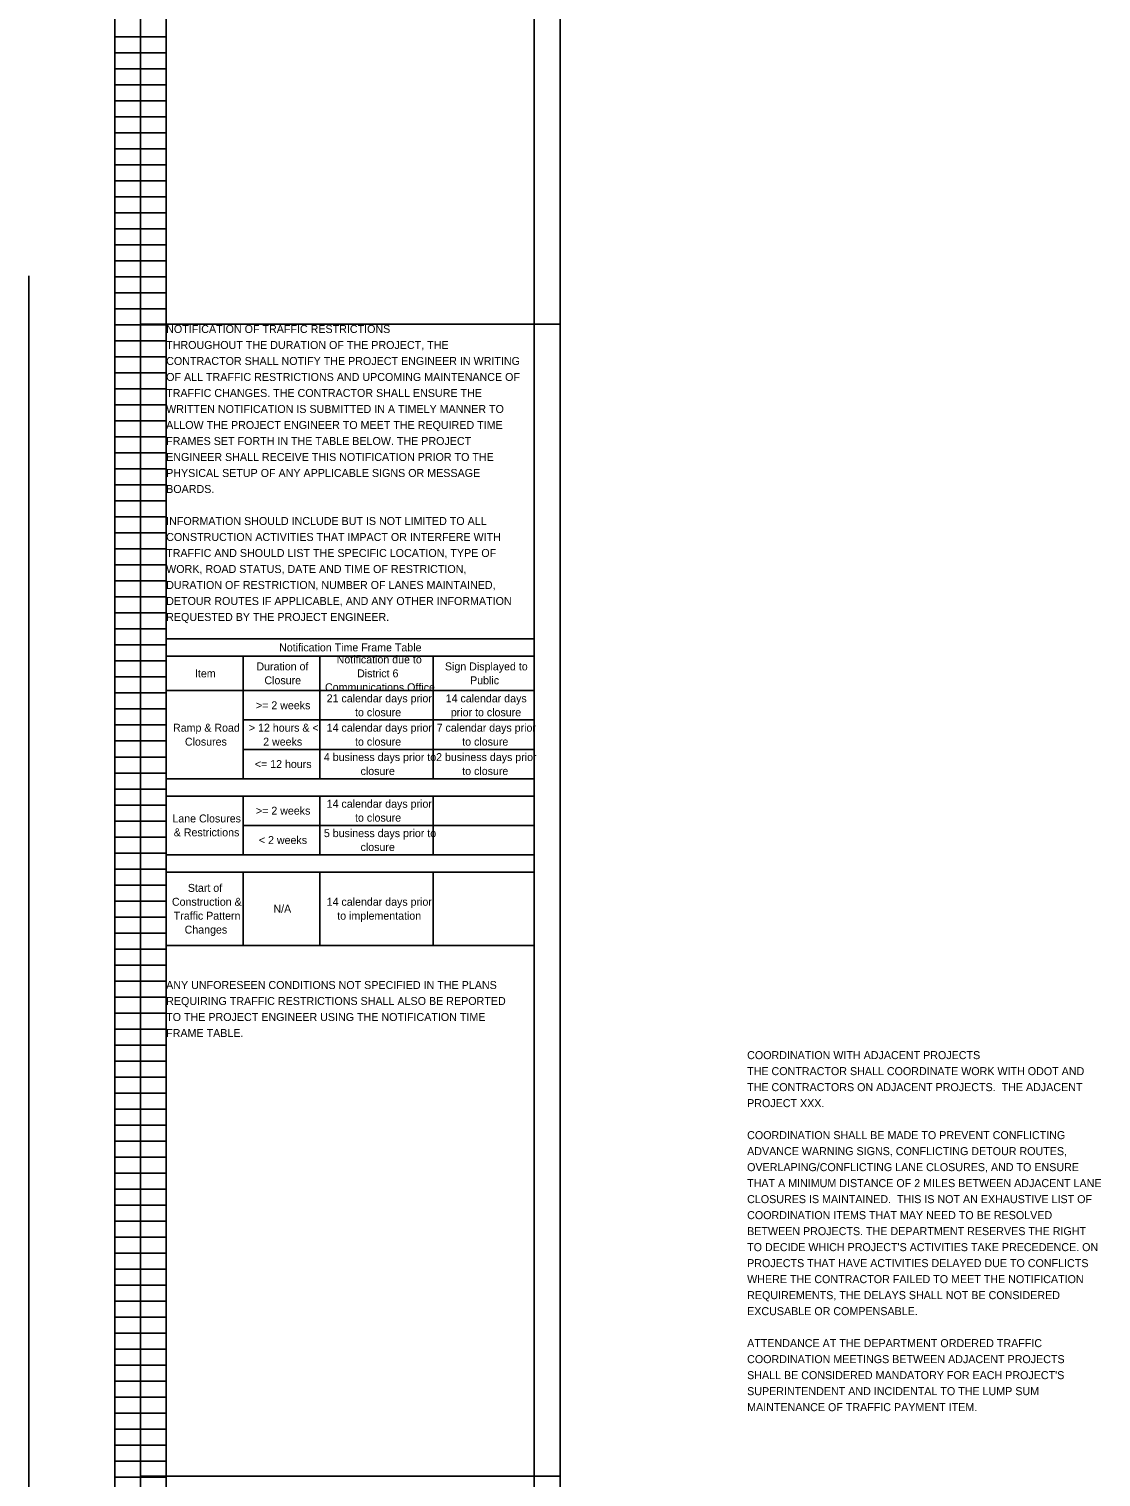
# Model space of a CAD drawing. Extents: x 0 to 19, y -301 to 22.
# Drawn here: x 0 to 18.75, y -79.66 to -54.32 of the extents above; entities that cross this region are included whole.
import ezdxf

# ---------------------------------------------------------------- set-up
doc = ezdxf.new("R2010")
doc.units = 0
doc.layers.add('SC_Scratch1', color=7, linetype='Continuous')
doc.layers.add('SH_Text', color=7, linetype='Continuous')

msp = doc.modelspace()

# ---------------------------------------------------------------- linework, layer by layer
at = {"layer": 'SC_Scratch1'}
for p, q in [((1.5, -59.5), (1.5, -39.34)), ((2.4, -59.5), (2.4, -39.34)), ((8.84, -59.5), (8.84, -39.34)), ((1.5, -54.46), (2.4, -54.46)), ((1.5, -54.74), (2.4, -54.74)), ((1.5, -55.02), (2.4, -55.02)), ((1.5, -55.3), (2.4, -55.3)), ((1.5, -55.58), (2.4, -55.58)), ((1.5, -55.86), (2.4, -55.86)), ((1.5, -56.14), (2.4, -56.14)), ((1.5, -56.42), (2.4, -56.42)), ((1.5, -56.7), (2.4, -56.7)), ((1.5, -56.98), (2.4, -56.98)), ((1.5, -57.26), (2.4, -57.26)), ((1.5, -57.54), (2.4, -57.54)), ((1.5, -57.82), (2.4, -57.82)), ((1.5, -58.1), (2.4, -58.1)), ((1.5, -58.38), (2.4, -58.38)), ((0, -58.64), (0, -80.64)), ((1.5, -58.66), (2.4, -58.66)), ((1.5, -58.94), (2.4, -58.94)), ((1.5, -59.22), (2.4, -59.22)), ((1.5, -59.5), (2.4, -59.5)), ((1.5, -59.5), (2.4, -59.5)), ((1.5, -79.66), (1.5, -59.5)), ((2.4, -79.66), (2.4, -59.5)), ((8.84, -79.66), (8.84, -59.5)), ((1.5, -59.78), (2.4, -59.78)), ((1.5, -60.06), (2.4, -60.06)), ((1.5, -60.34), (2.4, -60.34)), ((1.5, -60.62), (2.4, -60.62)), ((1.5, -60.9), (2.4, -60.9)), ((1.5, -61.18), (2.4, -61.18)), ((1.5, -61.46), (2.4, -61.46)), ((1.5, -61.74), (2.4, -61.74)), ((1.5, -62.02), (2.4, -62.02)), ((1.5, -62.3), (2.4, -62.3)), ((1.5, -62.58), (2.4, -62.58)), ((1.5, -62.86), (2.4, -62.86)), ((1.5, -63.14), (2.4, -63.14)), ((1.5, -63.42), (2.4, -63.42)), ((1.5, -63.7), (2.4, -63.7)), ((1.5, -63.98), (2.4, -63.98)), ((1.5, -64.26), (2.4, -64.26)), ((1.5, -64.54), (2.4, -64.54)), ((1.5, -64.82), (2.4, -64.82)), ((1.5, -65.1), (2.4, -65.1)), ((1.5, -65.38), (2.4, -65.38)), ((1.5, -65.66), (2.4, -65.66)), ((1.5, -65.94), (2.4, -65.94)), ((1.5, -66.22), (2.4, -66.22)), ((1.5, -66.5), (2.4, -66.5)), ((1.5, -66.78), (2.4, -66.78)), ((1.5, -67.06), (2.4, -67.06)), ((1.5, -67.34), (2.4, -67.34)), ((1.5, -67.62), (2.4, -67.62)), ((1.5, -67.9), (2.4, -67.9)), ((1.5, -68.18), (2.4, -68.18)), ((1.5, -68.46), (2.4, -68.46)), ((1.5, -68.74), (2.4, -68.74)), ((1.5, -69.02), (2.4, -69.02)), ((1.5, -69.3), (2.4, -69.3)), ((1.5, -69.58), (2.4, -69.58)), ((1.5, -69.86), (2.4, -69.86)), ((1.5, -70.14), (2.4, -70.14)), ((1.5, -70.42), (2.4, -70.42)), ((1.5, -70.7), (2.4, -70.7)), ((1.5, -70.98), (2.4, -70.98)), ((1.5, -71.26), (2.4, -71.26)), ((1.5, -71.54), (2.4, -71.54)), ((1.5, -71.82), (2.4, -71.82)), ((1.5, -72.1), (2.4, -72.1)), ((1.5, -72.38), (2.4, -72.38)), ((1.5, -72.66), (2.4, -72.66)), ((1.5, -72.94), (2.4, -72.94)), ((1.5, -73.22), (2.4, -73.22)), ((1.5, -73.5), (2.4, -73.5)), ((1.5, -73.78), (2.4, -73.78)), ((1.5, -74.06), (2.4, -74.06)), ((1.5, -74.34), (2.4, -74.34)), ((1.5, -74.62), (2.4, -74.62)), ((1.5, -74.9), (2.4, -74.9)), ((1.5, -75.18), (2.4, -75.18)), ((1.5, -75.46), (2.4, -75.46)), ((1.5, -75.74), (2.4, -75.74)), ((1.5, -76.02), (2.4, -76.02)), ((1.5, -76.3), (2.4, -76.3)), ((1.5, -76.58), (2.4, -76.58)), ((1.5, -76.86), (2.4, -76.86)), ((1.5, -77.14), (2.4, -77.14)), ((1.5, -77.42), (2.4, -77.42)), ((1.5, -77.7), (2.4, -77.7)), ((1.5, -77.98), (2.4, -77.98)), ((1.5, -78.26), (2.4, -78.26)), ((1.5, -78.54), (2.4, -78.54)), ((1.5, -78.82), (2.4, -78.82)), ((1.5, -79.1), (2.4, -79.1)), ((1.5, -79.38), (2.4, -79.38)), ((1.5, -79.66), (2.4, -79.66)), ((1.5, -79.66), (2.4, -79.66)), ((1.5, -99.82), (1.5, -79.66)), ((2.4, -99.82), (2.4, -79.66)), ((8.84, -99.82), (8.84, -79.66))]:
    msp.add_line(p, q, dxfattribs=at)
for points in [[(1.95, -39.323), (9.29, -39.323), (9.29, -59.483), (1.95, -59.483)], [(1.95, -59.483), (9.29, -59.483), (9.29, -79.643), (1.95, -79.643)], [(1.95, -79.643), (9.29, -79.643), (9.29, -99.803), (1.95, -99.803)]]:
    msp.add_lwpolyline(points, close=True, dxfattribs=at)
at = {"layer": 'SH_Text'}
for p, q in [((2.4, -64.991), (8.84, -64.991)), ((2.4, -64.991), (2.4, -70.358)), ((8.84, -64.991), (8.84, -70.358)), ((2.4, -65.294), (8.84, -65.294)), ((3.745, -65.294), (3.745, -67.44)), ((5.091, -65.294), (5.091, -67.44)), ((7.071, -65.294), (7.071, -67.44)), ((2.4, -65.898), (8.84, -65.898)), ((3.745, -66.412), (8.84, -66.412)), ((3.745, -66.926), (8.84, -66.926)), ((2.4, -67.44), (8.84, -67.44)), ((2.4, -67.743), (8.84, -67.743)), ((3.745, -67.743), (3.745, -68.771)), ((5.091, -67.743), (5.091, -68.771)), ((7.071, -67.743), (7.071, -68.771)), ((3.745, -68.257), (8.84, -68.257)), ((2.4, -68.771), (8.84, -68.771)), ((2.4, -69.073), (8.84, -69.073)), ((3.745, -69.073), (3.745, -70.358)), ((5.091, -69.073), (5.091, -70.358)), ((7.071, -69.073), (7.071, -70.358)), ((2.4, -70.358), (8.84, -70.358))]:
    msp.add_line(p, q, dxfattribs=at)

# ---------------------------------------------------------------- texts
for s, height, p in [('NOTIFICATION OF TRAFFIC RESTRICTIONS', 0.14, (2.4, -59.64)), ('THROUGHOUT THE DURATION OF THE PROJECT, THE ', 0.14, (2.4, -59.92)), ('CONTRACTOR SHALL NOTIFY THE PROJECT ENGINEER IN WRITING ', 0.14, (2.4, -60.2)), ('OF ALL TRAFFIC RESTRICTIONS AND UPCOMING MAINTENANCE OF ', 0.14, (2.4, -60.48)), ('TRAFFIC CHANGES. THE CONTRACTOR SHALL ENSURE THE ', 0.14, (2.4, -60.76)), ('WRITTEN NOTIFICATION IS SUBMITTED IN A TIMELY MANNER TO ', 0.14, (2.4, -61.04)), ('ALLOW THE PROJECT ENGINEER TO MEET THE REQUIRED TIME ', 0.14, (2.4, -61.32)), ('FRAMES SET FORTH IN THE TABLE BELOW. THE PROJECT ', 0.14, (2.4, -61.6)), ('ENGINEER SHALL RECEIVE THIS NOTIFICATION PRIOR TO THE ', 0.14, (2.4, -61.88)), ('PHYSICAL SETUP OF ANY APPLICABLE SIGNS OR MESSAGE ', 0.14, (2.4, -62.16)), ('BOARDS. ', 0.14, (2.4, -62.44)), ('INFORMATION SHOULD INCLUDE BUT IS NOT LIMITED TO ALL ', 0.14, (2.4, -63)), ('CONSTRUCTION ACTIVITIES THAT IMPACT OR INTERFERE WITH ', 0.14, (2.4, -63.28)), ('TRAFFIC AND SHOULD LIST THE SPECIFIC LOCATION, TYPE OF ', 0.14, (2.4, -63.56)), ('WORK, ROAD STATUS, DATE AND TIME OF RESTRICTION, ', 0.14, (2.4, -63.84)), ('DURATION OF RESTRICTION, NUMBER OF LANES MAINTAINED, ', 0.14, (2.4, -64.12)), ('DETOUR ROUTES IF APPLICABLE, AND ANY OTHER INFORMATION ', 0.14, (2.4, -64.4)), ('REQUESTED BY THE PROJECT ENGINEER.', 0.14, (2.4, -64.68)), ('Notification Time Frame Table', 0.13908, (4.376, -65.212)), ('Notification due to ', 0.13908, (5.383, -65.422)), ('Item', 0.1391, (2.904, -65.666)), ('Duration of ', 0.13908, (3.979, -65.544)), ('District 6 ', 0.13908, (5.74, -65.666)), ('Sign Displayed to ', 0.13908, (7.277, -65.544)), ('Closure', 0.1391, (4.119, -65.787)), ('Communications Office', 0.13908, (5.179, -65.909)), ('Public', 0.1391, (7.717, -65.787)), ('>= 2 weeks', 0.1391, (3.971, -66.225)), ('21 calendar days prior ', 0.13908, (5.208, -66.103)), ('14 calendar days ', 0.13908, (7.29, -66.103)), ('to closure', 0.1391, (5.704, -66.347)), ('prior to closure', 0.13908, (7.38, -66.347)), ('Ramp & Road ', 0.13908, (2.52, -66.617)), ('> 12 hours & < ', 0.13908, (3.847, -66.617)), ('14 calendar days prior ', 0.13908, (5.208, -66.617)), ('7 calendar days prior ', 0.13908, (7.132, -66.617)), ('Closures', 0.1391, (2.728, -66.861)), ('2 weeks', 0.1391, (4.097, -66.861)), ('to closure', 0.1391, (5.704, -66.861)), ('to closure', 0.1391, (7.579, -66.861)), ('<= 12 hours', 0.13908, (3.951, -67.253)), ('4 business days prior to ', 0.13908, (5.159, -67.131)), ('2 business days prior ', 0.13908, (7.122, -67.131)), ('closure', 0.1391, (5.801, -67.375)), ('to closure', 0.1391, (7.579, -67.375)), ('14 calendar days prior ', 0.13908, (5.208, -67.948)), ('Lane Closures ', 0.13908, (2.509, -68.205)), ('>= 2 weeks', 0.1391, (3.971, -68.069)), ('to closure', 0.1391, (5.704, -68.191)), ('& Restrictions', 0.13908, (2.533, -68.448)), ('5 business days prior to ', 0.13908, (5.159, -68.462)), ('< 2 weeks', 0.1391, (4.022, -68.583)), ('closure', 0.1391, (5.801, -68.705)), ('Start of ', 0.1391, (2.78, -69.42)), ('Construction & ', 0.13908, (2.501, -69.663)), ('N/A', 0.1391, (4.277, -69.785)), ('14 calendar days prior ', 0.13908, (5.208, -69.663)), ('Traffic Pattern ', 0.13908, (2.532, -69.907)), ('to implementation', 0.13908, (5.393, -69.907)), ('Changes', 0.1391, (2.723, -70.15)), ('ANY UNFORESEEN CONDITIONS NOT SPECIFIED IN THE PLANS ', 0.14, (2.4, -71.12)), ('REQUIRING TRAFFIC RESTRICTIONS SHALL ALSO BE REPORTED ', 0.14, (2.4, -71.4)), ('TO THE PROJECT ENGINEER USING THE NOTIFICATION TIME ', 0.14, (2.4, -71.68)), ('FRAME TABLE. ', 0.14, (2.4, -71.96)), ('COORDINATION WITH ADJACENT PROJECTS', 0.14, (12.563, -72.347)), ('THE CONTRACTOR SHALL COORDINATE WORK WITH ODOT AND ', 0.14, (12.563, -72.627)), ('THE CONTRACTORS ON ADJACENT PROJECTS.  THE ADJACENT ', 0.14, (12.563, -72.907)), ('PROJECT XXX.', 0.14, (12.563, -73.187)), ('COORDINATION SHALL BE MADE TO PREVENT CONFLICTING ', 0.14, (12.563, -73.747)), ('ADVANCE WARNING SIGNS, CONFLICTING DETOUR ROUTES, ', 0.14, (12.563, -74.027)), ('OVERLAPING/CONFLICTING LANE CLOSURES, AND TO ENSURE ', 0.14, (12.563, -74.307)), ('THAT A MINIMUM DISTANCE OF 2 MILES BETWEEN ADJACENT LANE ', 0.14, (12.563, -74.587)), ('CLOSURES IS MAINTAINED.  THIS IS NOT AN EXHAUSTIVE LIST OF ', 0.14, (12.563, -74.867)), ('COORDINATION ITEMS THAT MAY NEED TO BE RESOLVED ', 0.14, (12.563, -75.147)), ('BETWEEN PROJECTS. THE DEPARTMENT RESERVES THE RIGHT ', 0.14, (12.563, -75.427)), ("TO DECIDE WHICH PROJECT'S ACTIVITIES TAKE PRECEDENCE. ON ", 0.14, (12.563, -75.707)), ('PROJECTS THAT HAVE ACTIVITIES DELAYED DUE TO CONFLICTS ', 0.14, (12.563, -75.987)), ('WHERE THE CONTRACTOR FAILED TO MEET THE NOTIFICATION ', 0.14, (12.563, -76.267)), ('REQUIREMENTS, THE DELAYS SHALL NOT BE CONSIDERED ', 0.14, (12.563, -76.547)), ('EXCUSABLE OR COMPENSABLE.', 0.14, (12.563, -76.827)), ('ATTENDANCE AT THE DEPARTMENT ORDERED TRAFFIC ', 0.14, (12.563, -77.387)), ('COORDINATION MEETINGS BETWEEN ADJACENT PROJECTS ', 0.14, (12.563, -77.667)), ("SHALL BE CONSIDERED MANDATORY FOR EACH PROJECT'S ", 0.14, (12.563, -77.947)), ('SUPERINTENDENT AND INCIDENTAL TO THE LUMP SUM ', 0.14, (12.563, -78.227)), ('MAINTENANCE OF TRAFFIC PAYMENT ITEM.', 0.14, (12.563, -78.507))]:
    msp.add_text(s, height=height, dxfattribs=at).set_placement(p)

doc.saveas('drawing.dxf')
